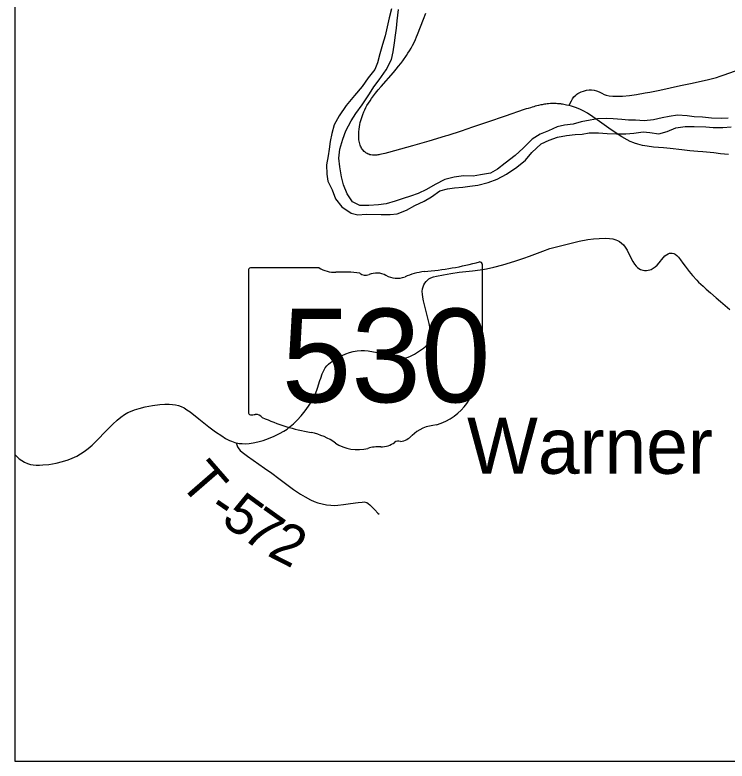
# Model space of a CAD drawing. Extents: x -10.5 to 40.6, y -3.2 to 22.
# Drawn here: x -10.544 to -9.541, y 14.1 to 15.152 of the extents above; entities that cross this region are included whole.
import ezdxf

# ---------------------------------------------------------------- set-up
doc = ezdxf.new("R2010")
doc.units = 0
for name, color, linetype in [('GM_X_Major_River', 7, 'Continuous'), ('GM_X_State_Route', 7, 'Continuous'), ('GM_X_State_Shield', 7, 'Continuous'), ('GM_X_Township_Road', 7, 'Continuous'), ('GM_X_Township_Road_Text', 7, 'Continuous'), ('GM_X_Unincorporated_Text', 7, 'Continuous'), ('SH_Text', 7, 'Continuous')]:
    doc.layers.add(name, color=color, linetype=linetype)

msp = doc.modelspace()

# ---------------------------------------------------------------- linework, layer by layer
at = {"layer": 'GM_X_Major_River'}
for points in [[(-10.0142, 15.1604), (-10.0175, 15.1475), (-10.0203, 15.1349), (-10.0232, 15.122), (-10.0268, 15.1098), (-10.0304, 15.0969), (-10.034, 15.0843), (-10.0377, 15.0748), (-10.047, 15.0629), (-10.0556, 15.051), (-10.066, 15.0383), (-10.078, 15.0241), (-10.088, 15.0096), (-10.0947, 14.9966), (-10.0983, 14.9844), (-10.1004, 14.9734), (-10.1018, 14.9627), (-10.1032, 14.9532), (-10.1056, 14.9403), (-10.1051, 14.9274), (-10.1038, 14.9172), (-10.0976, 14.9051), (-10.0929, 14.8923), (-10.084, 14.881), (-10.071, 14.8721), (-10.0615, 14.87), (-10.0497, 14.8709), (-10.0285, 14.8704), (-10.016, 14.8706), (-10.0061, 14.8711), (-9.9929, 14.8766), (-9.9813, 14.8832), (-9.9681, 14.8894), (-9.9576, 14.8953), (-9.9459, 14.9038), (-9.9353, 14.9066), (-9.9255, 14.9082), (-9.9138, 14.9091), (-9.9035, 14.9104), (-9.8926, 14.9117), (-9.8778, 14.9157), (-9.865, 14.9204), (-9.8522, 14.9274), (-9.8376, 14.9371), (-9.8252, 14.9471), (-9.8166, 14.9579), (-9.8031, 14.9698), (-9.7922, 14.9753), (-9.7801, 14.9792), (-9.7676, 14.9817), (-9.7555, 14.983), (-9.7457, 14.9835), (-9.7355, 14.9855), (-9.7226, 14.9853)], [(-9.7016, 15.0053), (-9.7115, 15.0056), (-9.724, 15.0054), (-9.7342, 15.0034), (-9.7467, 15.0009), (-9.7584, 14.9977), (-9.7705, 14.9961), (-9.7807, 14.994), (-9.7931, 14.9885), (-9.8045, 14.9838), (-9.8161, 14.9768), (-9.8288, 14.9641), (-9.8397, 14.9534), (-9.8539, 14.9426), (-9.8648, 14.9345), (-9.8746, 14.9286), (-9.8886, 14.9265), (-9.8988, 14.9245), (-9.9125, 14.9247), (-9.9257, 14.923), (-9.9389, 14.9198), (-9.9525, 14.9128), (-9.9649, 14.9058), (-9.9766, 14.8999), (-9.9875, 14.896), (-9.9977, 14.8928), (-10.0087, 14.8893), (-10.0215, 14.8853), (-10.0325, 14.884), (-10.0461, 14.8831), (-10.0586, 14.8833), (-10.0689, 14.8881), (-10.0767, 14.8997), (-10.0818, 14.9122), (-10.0846, 14.9235), (-10.087, 14.9375), (-10.0883, 14.9496), (-10.087, 14.9626), (-10.0826, 14.9767), (-10.0782, 14.9885), (-10.0708, 15.0026), (-10.0642, 15.0126), (-10.0552, 15.0248), (-10.0452, 15.0405), (-10.0389, 15.0505), (-10.0314, 15.0604), (-10.0214, 15.0742), (-10.014, 15.0887), (-10.0115, 15.0998), (-10.0098, 15.1123), (-10.0084, 15.1233), (-10.007, 15.1328), (-10.006, 15.1435), (-10.004, 15.1591)], [(-9.5397, 15.0064), (-9.5492, 15.0059), (-9.5633, 15.0064), (-9.5758, 15.0078), (-9.5879, 15.008), (-9.5974, 15.0094), (-9.6111, 15.0103), (-9.6228, 15.0083), (-9.633, 15.0066), (-9.6451, 15.0038), (-9.658, 15.0025), (-9.6705, 15.0035), (-9.68, 15.0033), (-9.6895, 15.0044), (-9.7016, 15.0053)], [(-9.7226, 14.9853), (-9.7104, 14.9847), (-9.6972, 14.9841), (-9.6839, 14.9843), (-9.6725, 14.9849), (-9.6597, 14.9869), (-9.6502, 14.9859), (-9.6376, 14.9842), (-9.6256, 14.9874), (-9.6135, 14.9925), (-9.6006, 14.9942), (-9.5877, 14.9944), (-9.5714, 14.9938), (-9.5612, 14.9932), (-9.5475, 14.993), (-9.5354, 14.9939)]]:
    msp.add_lwpolyline(points, dxfattribs=at)
at = {"layer": 'GM_X_State_Route'}
for points in [[(-9.9615, 14.9738), (-9.9745, 14.9701), (-9.9846, 14.9672), (-10.0181, 14.958), (-10.0235, 14.9566), (-10.0306, 14.9549), (-10.032, 14.9546), (-10.0332, 14.9544), (-10.0345, 14.9542), (-10.0367, 14.954), (-10.0388, 14.9539), (-10.0409, 14.954), (-10.0431, 14.9543), (-10.0446, 14.9547), (-10.0461, 14.9552), (-10.0471, 14.9556), (-10.0482, 14.9562), (-10.0492, 14.9567), (-10.0502, 14.9574), (-10.0513, 14.9582), (-10.0525, 14.9593), (-10.0545, 14.9615), (-10.0553, 14.9627), (-10.0562, 14.964), (-10.0569, 14.9652), (-10.0575, 14.9666), (-10.0582, 14.9682), (-10.0588, 14.97), (-10.0596, 14.9736), (-10.0599, 14.9756), (-10.0601, 14.9777), (-10.0602, 14.9803), (-10.0601, 14.9833), (-10.0599, 14.9871), (-10.0596, 14.9906), (-10.0592, 14.9939), (-10.0586, 14.9973), (-10.058, 15.0001), (-10.0573, 15.0027), (-10.0565, 15.0057), (-10.0556, 15.0086), (-10.0545, 15.0114), (-10.0531, 15.0149), (-10.0518, 15.0178), (-10.0502, 15.021), (-10.0486, 15.024), (-10.0465, 15.0274), (-10.0443, 15.0307), (-10.042, 15.0341), (-10.0394, 15.0377), (-10.0365, 15.0415), (-10.0328, 15.0461), (-10.0286, 15.051), (-10.0114, 15.0707), (-10.0076, 15.0752), (-10.0042, 15.0793), (-10.0009, 15.0834), (-9.9981, 15.0871), (-9.9931, 15.0943), (-9.9909, 15.0977), (-9.9887, 15.1011), (-9.9865, 15.1049), (-9.9844, 15.1088), (-9.9822, 15.113), (-9.9802, 15.1171), (-9.9787, 15.1207), (-9.9773, 15.124), (-9.9691, 15.1455), (-9.9657, 15.1541)], [(-9.6718, 14.971), (-9.6727, 14.9713), (-9.6778, 14.9734), (-9.6823, 14.9756), (-9.6897, 14.9799), (-9.699, 14.986), (-9.7077, 14.9921), (-9.7209, 15.0013), (-9.7244, 15.0039), (-9.7305, 15.0082), (-9.7378, 15.013), (-9.7433, 15.0161), (-9.7489, 15.0188), (-9.7548, 15.0211), (-9.7604, 15.0229), (-9.7638, 15.0238), (-9.7674, 15.0247), (-9.7694, 15.0251), (-9.7713, 15.0255), (-9.773, 15.0258), (-9.7744, 15.026), (-9.7757, 15.0262), (-9.7774, 15.0263), (-9.7789, 15.0265), (-9.7804, 15.0266), (-9.7821, 15.0267), (-9.7842, 15.0268), (-9.7868, 15.0268), (-9.7886, 15.0268), (-9.7901, 15.0267), (-9.7929, 15.0264), (-9.7949, 15.0262), (-9.7967, 15.026), (-9.7985, 15.0257), (-9.8002, 15.0255), (-9.8019, 15.0251), (-9.8037, 15.0248), (-9.8071, 15.024), (-9.8094, 15.0235), (-9.8116, 15.0229), (-9.8137, 15.0223), (-9.8157, 15.0217), (-9.8185, 15.0209), (-9.8215, 15.02), (-9.8243, 15.0191), (-9.827, 15.0182), (-9.8541, 15.009), (-9.8788, 15.0006), (-9.9, 14.9934), (-9.9158, 14.988), (-9.9347, 14.9819), (-9.9383, 14.9808), (-9.9615, 14.9738)], [(-9.5394, 14.9548), (-9.5505, 14.9561), (-9.5598, 14.9571), (-9.5753, 14.9585), (-9.5827, 14.9592), (-9.5938, 14.9602), (-9.6049, 14.9615), (-9.6216, 14.9633), (-9.6309, 14.9642), (-9.6451, 14.9655), (-9.6537, 14.9665), (-9.6604, 14.9677), (-9.6669, 14.9693), (-9.6718, 14.971)], [(-10.5445, 14.532), (-10.5439, 14.5313), (-10.5402, 14.5279), (-10.5383, 14.5262), (-10.5347, 14.5236), (-10.5309, 14.5214), (-10.5268, 14.5196), (-10.5226, 14.5182), (-10.5188, 14.5175), (-10.5144, 14.5171), (-10.51, 14.5171), (-10.505, 14.5174), (-10.4969, 14.5181), (-10.4865, 14.52), (-10.4774, 14.5222), (-10.4696, 14.5247), (-10.4638, 14.5269), (-10.4575, 14.5299), (-10.4521, 14.5329), (-10.4468, 14.5363), (-10.4413, 14.5405), (-10.4356, 14.5454), (-10.4289, 14.552), (-10.4159, 14.5654), (-10.4064, 14.5751), (-10.4005, 14.5806), (-10.3953, 14.5849), (-10.3902, 14.5883), (-10.3855, 14.5911), (-10.3816, 14.5929), (-10.3759, 14.5952), (-10.3694, 14.5971), (-10.361, 14.5991), (-10.3507, 14.601), (-10.3403, 14.6025), (-10.3335, 14.603), (-10.3274, 14.6031), (-10.3225, 14.6028), (-10.3183, 14.6022), (-10.3142, 14.6011), (-10.3102, 14.5997), (-10.3063, 14.5978), (-10.3022, 14.5953), (-10.2977, 14.5921), (-10.2856, 14.5823), (-10.2715, 14.5711), (-10.262, 14.5641), (-10.2532, 14.5582), (-10.2478, 14.5549), (-10.2422, 14.552), (-10.2396, 14.5509), (-10.237, 14.5499), (-10.2349, 14.5492), (-10.2327, 14.5486), (-10.2307, 14.5482), (-10.2285, 14.5478), (-10.2266, 14.5475), (-10.2246, 14.5474), (-10.2202, 14.5473), (-10.2145, 14.5477), (-10.2089, 14.5485), (-10.2022, 14.55), (-10.195, 14.552), (-10.1873, 14.5547), (-10.1792, 14.558), (-10.1718, 14.5615), (-10.1658, 14.5649), (-10.1611, 14.568), (-10.1566, 14.5714), (-10.1519, 14.5755), (-10.147, 14.5803), (-10.1411, 14.5868), (-10.1356, 14.5937), (-10.1308, 14.6002), (-10.1271, 14.606), (-10.1238, 14.6121), (-10.1211, 14.6178), (-10.1183, 14.6254), (-10.1149, 14.6362), (-10.1137, 14.6396), (-10.1115, 14.646), (-10.1095, 14.6504), (-10.1073, 14.6541), (-10.1051, 14.6569), (-10.1026, 14.6595), (-10.0998, 14.6619), (-10.0958, 14.6647), (-10.0895, 14.6686), (-10.0835, 14.6717), (-10.0785, 14.674), (-10.0733, 14.6758), (-10.068, 14.6772), (-10.0625, 14.6781), (-10.057, 14.6785), (-10.0522, 14.6785), (-10.0467, 14.6781), (-10.0394, 14.6769), (-10.0315, 14.6752), (-10.0124, 14.6698), (-10.0057, 14.6683), (-10.0006, 14.6678), (-9.9968, 14.6679), (-9.9937, 14.6684), (-9.9906, 14.6693), (-9.9871, 14.6706), (-9.9815, 14.6736), (-9.9747, 14.678), (-9.969, 14.682), (-9.9666, 14.6841), (-9.964, 14.6869), (-9.9623, 14.6897), (-9.9613, 14.6913), (-9.9602, 14.6943), (-9.9595, 14.6961), (-9.9594, 14.6968), (-9.959, 14.7006), (-9.959, 14.7037), (-9.9596, 14.7094), (-9.961, 14.7167), (-9.9647, 14.7318), (-9.9689, 14.7486), (-9.9701, 14.754), (-9.9706, 14.7583), (-9.9707, 14.7619), (-9.9703, 14.7654), (-9.9696, 14.7683), (-9.9685, 14.7711), (-9.9671, 14.7737), (-9.9653, 14.776), (-9.9631, 14.7781), (-9.9613, 14.7795), (-9.9586, 14.7809), (-9.9547, 14.7824), (-9.9506, 14.7836), (-9.9408, 14.7854), (-9.9305, 14.7873), (-9.9189, 14.7889), (-9.8998, 14.7911), (-9.8893, 14.7924), (-9.8801, 14.794), (-9.8697, 14.7962), (-9.8571, 14.7995), (-9.8404, 14.8045), (-9.8275, 14.8088), (-9.8199, 14.8116), (-9.8008, 14.8189), (-9.7909, 14.8223), (-9.7796, 14.8255), (-9.7646, 14.8292), (-9.7495, 14.8326), (-9.7373, 14.835), (-9.7294, 14.8361), (-9.7214, 14.8367), (-9.7133, 14.8369), (-9.7072, 14.8367), (-9.7024, 14.836), (-9.6983, 14.8349), (-9.6956, 14.8337), (-9.693, 14.8323), (-9.6901, 14.8302), (-9.6875, 14.8276), (-9.6849, 14.8243), (-9.6823, 14.8202), (-9.6786, 14.8131), (-9.674, 14.8042), (-9.6717, 14.8005), (-9.6694, 14.7975), (-9.6676, 14.7957), (-9.6655, 14.7942), (-9.6632, 14.793), (-9.6602, 14.7919), (-9.6577, 14.7915), (-9.6551, 14.7914), (-9.6525, 14.7917), (-9.6501, 14.7923), (-9.6483, 14.793), (-9.6454, 14.7946), (-9.6428, 14.7965), (-9.64, 14.7991), (-9.6371, 14.8023), (-9.6352, 14.8046), (-9.6337, 14.8066), (-9.631, 14.8098), (-9.6289, 14.812), (-9.6265, 14.8137), (-9.6245, 14.8149), (-9.6223, 14.8157), (-9.6201, 14.816), (-9.6185, 14.816), (-9.6165, 14.8154), (-9.6145, 14.8145), (-9.6123, 14.8128), (-9.6099, 14.8102), (-9.6069, 14.8064), (-9.6036, 14.8019), (-9.6004, 14.7974), (-9.5948, 14.7899), (-9.5903, 14.7846), (-9.584, 14.7778), (-9.5814, 14.7751), (-9.5752, 14.7692), (-9.5743, 14.7684), (-9.5709, 14.7651), (-9.5648, 14.7599), (-9.5568, 14.7531), (-9.5507, 14.7479), (-9.5377, 14.7364)]]:
    msp.add_lwpolyline(points, dxfattribs=at)
at = {"layer": 'GM_X_State_Shield'}
for p, q in [((-9.8861, 14.6955), (-9.8861, 14.8002)), ((-10.2157, 14.7918), (-10.2157, 14.5917)), ((-10.116, 14.7953), (-10.2125, 14.7953)), ((-9.8862, 14.6955), (-9.8861, 14.6955))]:
    msp.add_line(p, q, dxfattribs=at)
for centre, major_axis, start_param, end_param in [((-10.0035, 15.0681), (0.3495, 0), 4.814394, 5.042369), ((-9.8898, 14.8006), (0.00367, 0), 6.141152, 7.989035), ((-10.2119, 14.7922), (0.00382, 0), 1.712693, 3.28349), ((-10.093, 14.8185), (0.037, 0), 4.042523, 4.731795), ((-10.0807, 14.6829), (0.133, 0), 1.404758, 1.657858), ((-10.0505, 14.7933), (0.0107, 0), 3.836095, 5.185415), ((-10.0348, 14.7701), (0.0222, 0), 0.950623, 2.079405), ((-9.959, 14.7341), (0.0703, 0), 1.699011, 2.107814), ((-10.0062, 14.8019), (0.0267, 0), 4.081561, 5.145723), ((-9.887, 14.6878), (0.00568, 0), 1.883978, 3.671073), ((-9.8901, 14.6951), (0.00393, 0), 5.05454, 6.418171), ((-9.9231, 14.6746), (0.0341, 0), 5.934695, 6.695948), ((-9.873, 14.6517), (0.0248, 0), 2.387724, 3.262537), ((-9.984, 14.6384), (0.0874, 0), 5.101752, 6.440018), ((-10.2119, 14.5912), (0.00385, 0), 3.00124, 4.508301), ((-10.2113, 14.6117), (0.0294, 0), 4.665946, 4.897461), ((-10.2053, 14.5801), (0.0106, 0), 0.519207, 1.627899), ((-10.0715, 14.7599), (0.2524, 0), 4.195997, 4.488961), ((-9.9471, 14.5355), (0.0479, 0), 1.647645, 2.488434), ((-10.1467, 14.5018), (0.079, 0), 0.823519, 1.323587), ((-10.0078, 14.5723), (0.0282, 0), 4.937069, 5.64225), ((-10.0613, 14.5791), (0.0501, 0), 4.026481, 4.996735), ((-10.0287, 14.5642), (0.0267, 0), 4.691044, 5.507374), ((-10.0046, 14.5448), (0.00752, 0), 1.147584, 2.315152), ((-10.0324, 14.51), (0.0412, 0), 1.495662, 1.94098)]:
    msp.add_ellipse(centre, major_axis=major_axis, ratio=0.8, start_param=start_param, end_param=end_param, dxfattribs=at)
at = {"layer": 'GM_X_Township_Road'}
for points in [[(-9.6962, 15.037), (-9.6887, 15.0372), (-9.6788, 15.0382), (-9.669, 15.0395), (-9.6568, 15.0417), (-9.6502, 15.0429), (-9.6362, 15.0456), (-9.6071, 15.0521), (-9.5907, 15.0557), (-9.5676, 15.0606), (-9.5564, 15.0635), (-9.5511, 15.0652), (-9.5471, 15.0666), (-9.5296, 15.073)], [(-9.7638, 15.0238), (-9.7623, 15.0271), (-9.7607, 15.0304), (-9.7591, 15.0334), (-9.757, 15.0363), (-9.7545, 15.0387), (-9.753, 15.0399), (-9.7515, 15.0409), (-9.747, 15.0431), (-9.7435, 15.0444), (-9.7393, 15.0454), (-9.7356, 15.0459), (-9.7325, 15.0459), (-9.7288, 15.0454), (-9.7252, 15.0445), (-9.7217, 15.0433), (-9.7178, 15.0414), (-9.7145, 15.0397), (-9.7116, 15.0386), (-9.7073, 15.0377), (-9.7024, 15.0372), (-9.6962, 15.037)], [(-10.2327, 14.5486), (-10.2318, 14.5456), (-10.2309, 14.5431), (-10.2302, 14.5416), (-10.2293, 14.54), (-10.2272, 14.5377), (-10.2245, 14.5352), (-10.217, 14.5297), (-10.193, 14.513), (-10.1828, 14.5058), (-10.1728, 14.4985), (-10.1519, 14.4829), (-10.1422, 14.4761), (-10.1358, 14.4723), (-10.1281, 14.4683), (-10.123, 14.466), (-10.1177, 14.4641), (-10.1117, 14.4625), (-10.1056, 14.4613), (-10.0995, 14.4605), (-10.0945, 14.4603), (-10.0896, 14.4606), (-10.0816, 14.4617), (-10.0717, 14.4631), (-10.0612, 14.4644), (-10.0553, 14.4651), (-10.0526, 14.4653), (-10.0508, 14.465), (-10.049, 14.4644), (-10.0469, 14.4631), (-10.0445, 14.4612), (-10.0376, 14.454), (-10.0333, 14.4495), (-10.0315, 14.4478)]]:
    msp.add_lwpolyline(points, dxfattribs=at)
at = {"layer": 'SH_Text'}
msp.add_lwpolyline([(-10.5445, 16.0741), (-10.5445, 14.1), (-6.2122, 14.1)], dxfattribs=at)

# ---------------------------------------------------------------- texts
at = {"layer": 'GM_X_State_Shield'}
msp.add_text('530', height=0.13184, dxfattribs=at).set_placement((-10.1688, 14.6058))
at = {"layer": 'GM_X_Township_Road_Text'}
for s, rotation, p in [('T', 310.9876, (-10.3145, 14.4919)), ('5', 323.9263, (-10.2559, 14.4364)), ('-', 325.7054, (-10.2748, 14.4493)), ('7', 324.5879, (-10.227, 14.4154)), ('2', 332.9562, (-10.1908, 14.3904))]:
    msp.add_text(s, height=0.0568, rotation=rotation, dxfattribs=at).set_placement(p)
at = {"layer": 'GM_X_Unincorporated_Text'}
msp.add_text('Warner', height=0.07898, rotation=0, dxfattribs=at).set_placement((-9.9076, 14.5049))

doc.saveas('drawing.dxf')
